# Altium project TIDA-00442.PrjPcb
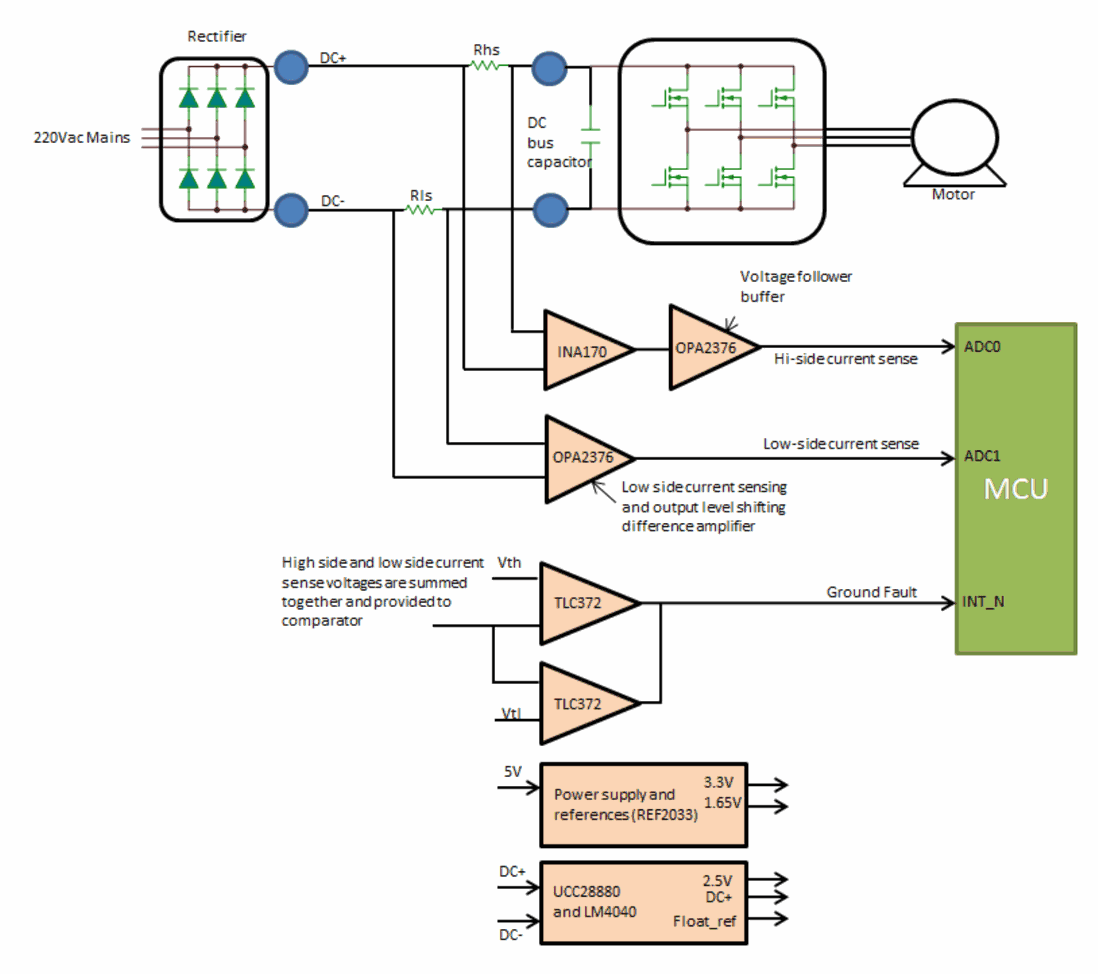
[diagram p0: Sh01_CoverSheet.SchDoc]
CopyrightYear: 2015; EVM_Orderable: N/A; PCB_Layout: Manjunath M; PCB_Rev: E2; PRJ_Customer: Public Release; PRJ_Engineer: Pawan N; PRJ_Number: TIDA-00442; PRJ_Title: Ground Fault Protection for 220Vac Powered Drives; SCH_Rev: E2; TechSupport: http://www.ti.com/support; TIDA: 00442
3 sheets, 96 parts. Net scope: flat (ports and power ports of the same name join across sheets).
Board file: TIDA-00442.PcbDoc
Sheets:
  Sh01_CoverSheet.SchDoc
  Sh02_Current_sense.SchDoc
  Sh03_TID_Hardware.SchDoc

## Sheet Sh01_CoverSheet.SchDoc: Block Diagram
size 431 x 279 mm; Date: Not shown in title block; ApprovedBy: Not shown in title block; CheckedBy: Not shown in title block; Author: Not shown in title block; CompanyName: Not shown in title block; DrawnBy: Pawan N; Engineer: Not shown in title block; Organization: Not shown in title block; Address1: Not shown in title block; Address2: Not shown in title block; Address3: Not shown in title block; Address4: Not shown in title block; DocumentNumber: 1; Revision: Use project parameter SCH_Rev; SheetNumber: 1; SheetTotal: 3; PageSetup: Record=PageOptions¦CenterHorizontal=True¦CenterVertical=True¦PrintScale=1.00¦XCorrection=1.00¦YCorrection=1.00¦PrintKind=0¦BorderSize=5000000¦LeftOffset=0¦BottomOffset=0¦Orientation=2¦PaperLength=1000¦PaperWidth=1000¦Scale=100¦PaperSource=15¦PrintQuality=600¦MediaType=1¦DitherType=10¦PaperKind=Letter¦PrintScaleMode=1

## Sheet Sh02_Current_sense.SchDoc: Current sense and Signal Conditioning
size 431 x 279 mm; Date: Not shown in title block; ApprovedBy: Not shown in title block; CheckedBy: Not shown in title block; Author: Not shown in title block; CompanyName: Not shown in title block; DrawnBy: Pawan N; Engineer: Not shown in title block; Organization: Not shown in title block; Address1: Not shown in title block; Address2: Not shown in title block; Address3: Not shown in title block; Address4: Not shown in title block; DocumentNumber: 1; Revision: Use project parameter SCH_Rev; SheetNumber: 2; SheetTotal: 3; PageSetup: Record=PageOptions¦CenterHorizontal=True¦CenterVertical=True¦PrintScale=0.64¦XCorrection=1.00¦YCorrection=1.00¦PrintKind=0¦BorderSize=5000000¦LeftOffset=0¦BottomOffset=0¦Orientation=2¦PaperLength=1000¦PaperWidth=1000¦Scale=100¦PaperSource=15¦PrintQuality=600¦MediaType=1¦DitherType=10¦PrintScaleMode=1¦PaperKind=Letter¦PaperIndex=1
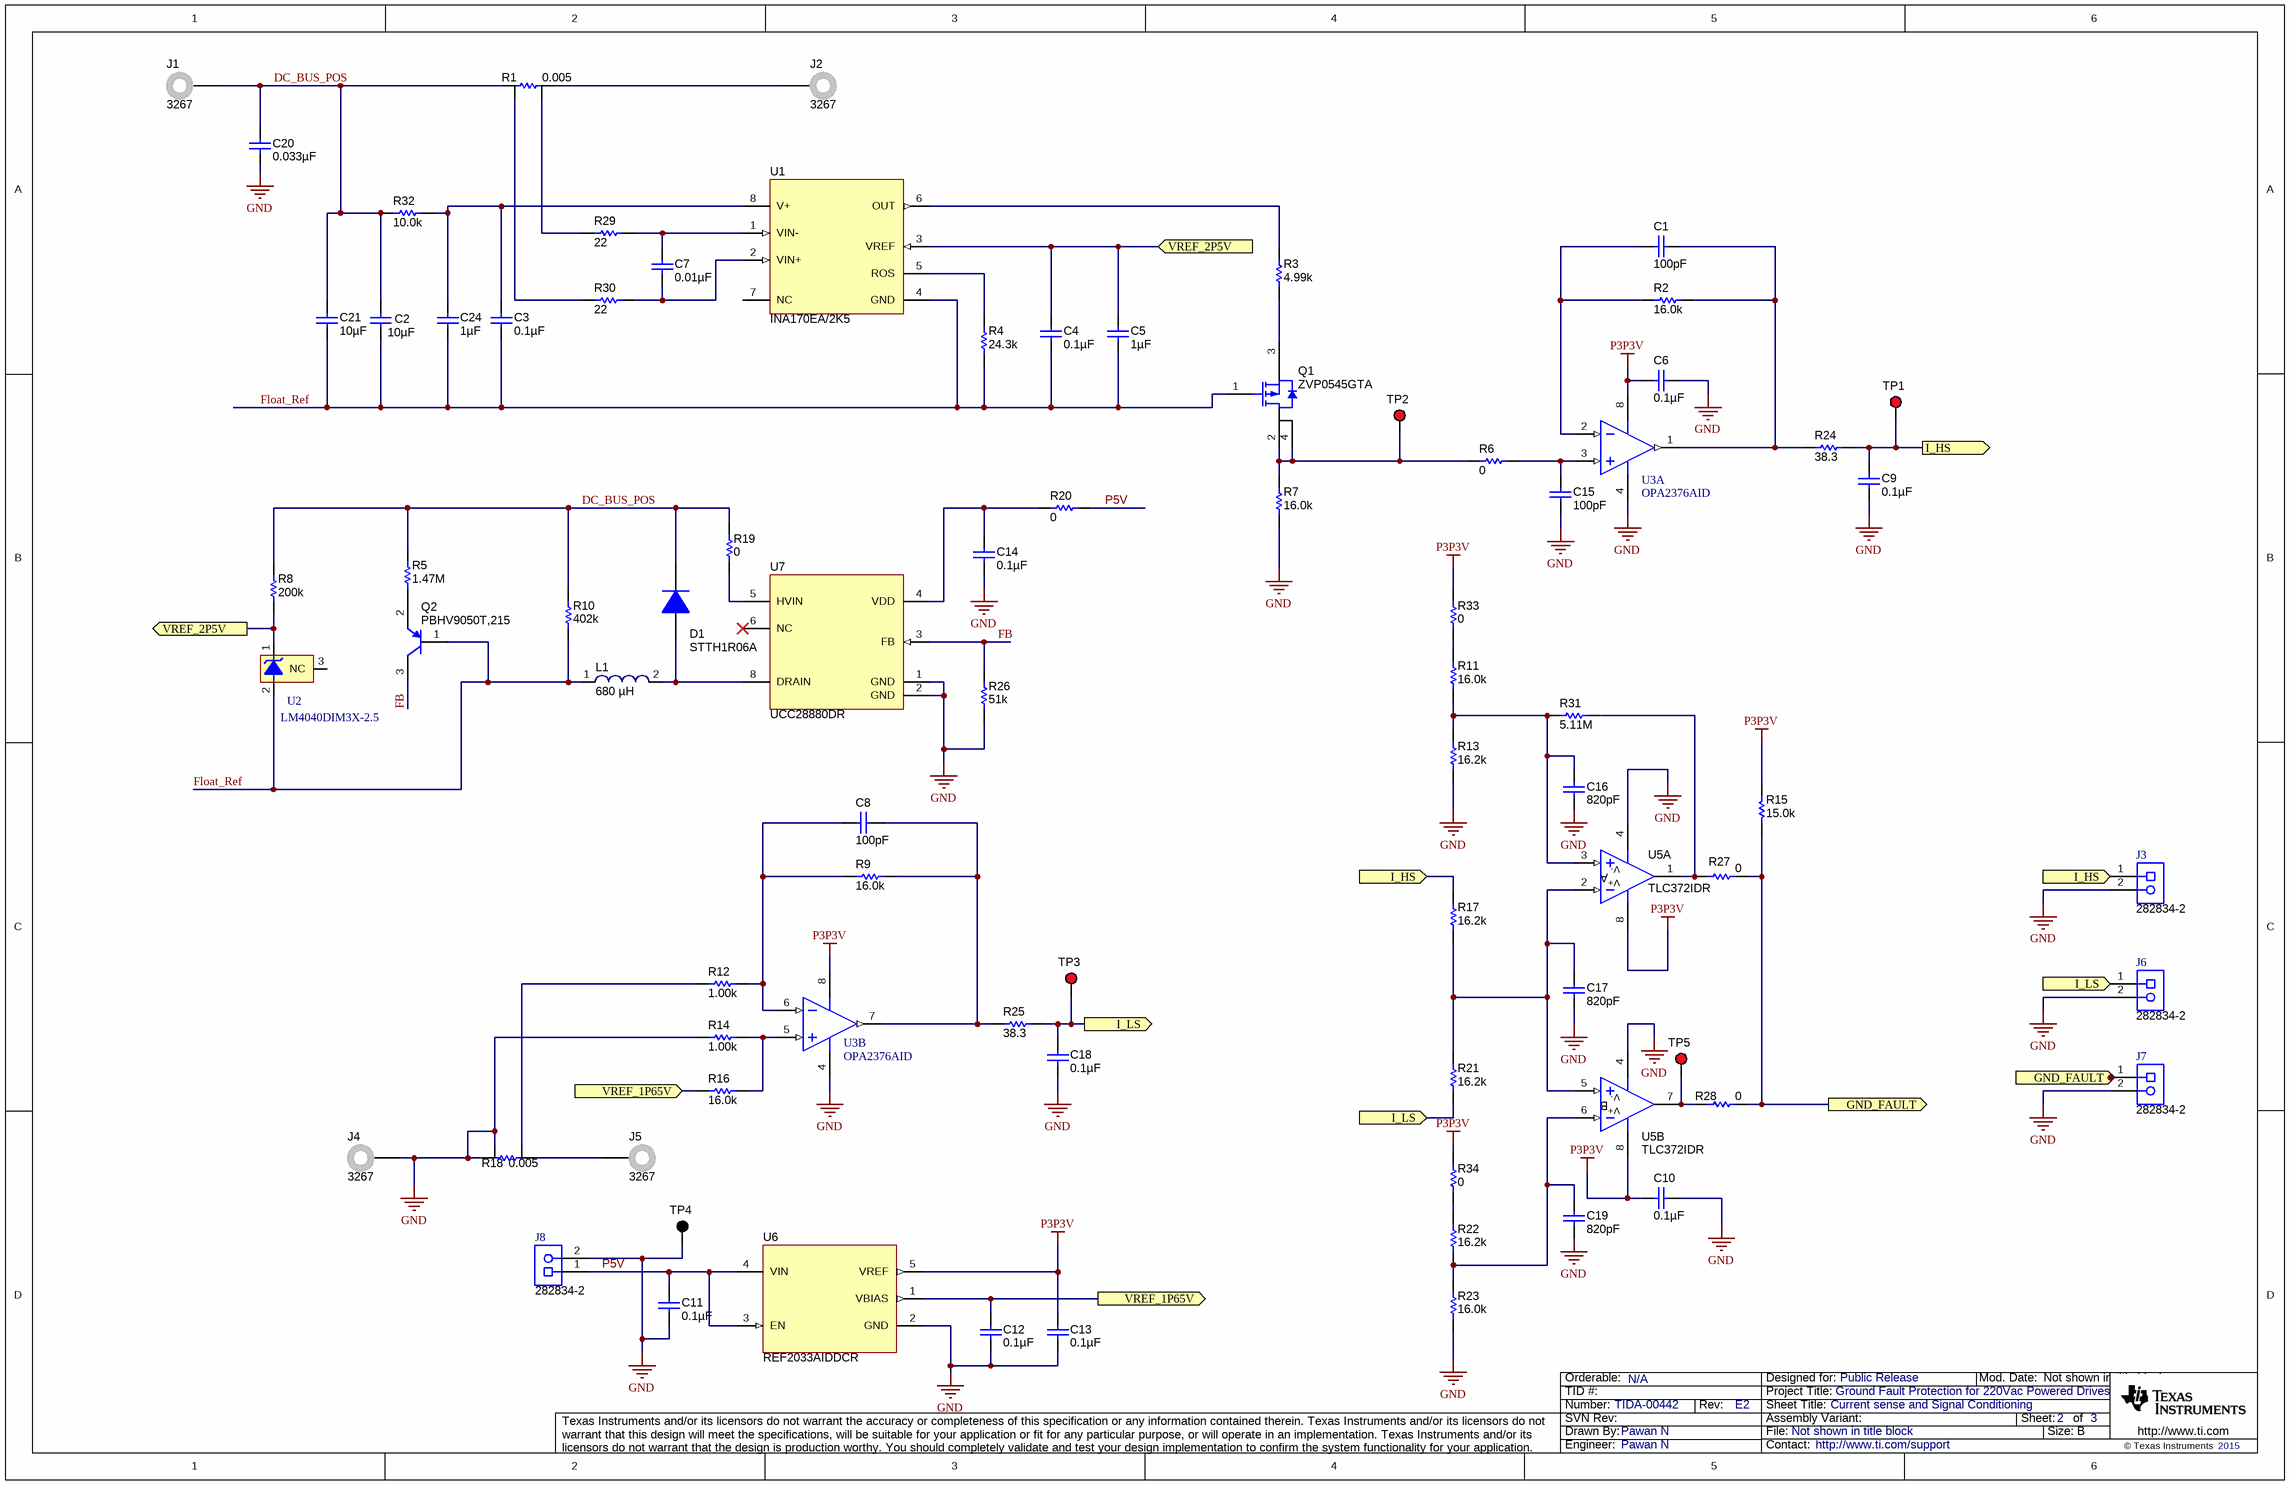
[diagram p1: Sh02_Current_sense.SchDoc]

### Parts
C1  ValueDisplayed: 100pF  [0603]  (hidden comment: GRM1885C1H101JA01D)
C2  ValueDisplayed: 10µF  [1206_190]  (hidden comment: CL31A106KBHNNNE)
C3  ValueDisplayed: 0.1µF  [0603]  (hidden comment: GRM188R71H104KA93D)
C4  ValueDisplayed: 0.1µF  [0603]  (hidden comment: GRM188R71H104KA93D)
C5  ValueDisplayed: 1µF  [0805_HV]  (hidden comment: GRM21BR71H105KA12L)
C6  ValueDisplayed: 0.1µF  [0603]  (hidden comment: GRM188R71H104KA93D)
C7  ValueDisplayed: 0.01µF  [0603]  (hidden comment: 0603ZC103KAT2A)
C8  ValueDisplayed: 100pF  [0603]  (hidden comment: GRM1885C1H101JA01D)
C9  ValueDisplayed: 0.1µF  [0603]  (hidden comment: GRM188R71H104KA93D)
C10  ValueDisplayed: 0.1µF  [0603]  (hidden comment: GRM188R71H104KA93D)
C11  ValueDisplayed: 0.1µF  [0603]  (hidden comment: GRM188R71H104KA93D)
C12  ValueDisplayed: 0.1µF  [0603]  (hidden comment: GRM188R71H104KA93D)
C13  ValueDisplayed: 0.1µF  [0603]  (hidden comment: GRM188R71H104KA93D)
C14  ValueDisplayed: 0.1µF  [0603]  (hidden comment: GRM188R71H104KA93D)
C15  ValueDisplayed: 100pF  [0603]  (hidden comment: GRM1885C1H101JA01D)
C16  ValueDisplayed: 820pF  [0603]  (hidden comment: GRM188R71H821KA01D)
C17  ValueDisplayed: 820pF  [0603]  (hidden comment: GRM188R71H821KA01D)
C18  ValueDisplayed: 0.1µF  [0603]  (hidden comment: GRM188R71H104KA93D)
C19  ValueDisplayed: 820pF  [0603]  (hidden comment: GRM188R71H821KA01D)
C20  ValueDisplayed: 0.033µF  [ECQE_1200x1290x600]  (hidden comment: ECQ-E6333KF)
C21  ValueDisplayed: 10µF  [1206_190]  (hidden comment: CL31A106KBHNNNE)
C24  ValueDisplayed: 1µF  [0805_HV]  (hidden comment: 08055C105KAT2A)
D1  STTH1R06A  [SMA]
J1  3267  [Pomona_3267]
J2  3267  [Pomona_3267]
J3  282834-2  [TEC_282834-2]
J4  3267  [Pomona_3267]
J5  3267  [Pomona_3267]
J6  282834-2  [TEC_282834-2]
J7  282834-2  [TEC_282834-2]
J8  282834-2  [TEC_282834-2]
L1  680 µH  [8095]
Q1  ZVP0545GTA  [SOT-223]
Q2  PBHV9050T,215  [SOT-23]
R1  ValueDisplayed: 0.005  [WSL3637_0.001]  (hidden comment: WSL36375L000FEA)
R2  ValueDisplayed: 16.0k  [0603]  (hidden comment: RC0603FR-0716KL)
R3  ValueDisplayed: 4.99k  [0603]  (hidden comment: CRCW06034K99FKEA)
R4  ValueDisplayed: 24.3k  [0603]  (hidden comment: RT0603BRD0724K3L)
R5  ValueDisplayed: 1.47M  [0603]  (hidden comment: CRCW06031M47FKEA)
R6  ValueDisplayed: 0  [0603]  (hidden comment: RC0603JR-070RL)
R7  ValueDisplayed: 16.0k  [0603]  (hidden comment: RG1608P-163-B-T5)
R8  ValueDisplayed: 200k  [0603]  (hidden comment: CRCW0603200KFKEA)
R9  ValueDisplayed: 16.0k  [0603]  (hidden comment: RG1608P-163-B-T5)
R10  ValueDisplayed: 402k  [0603]  (hidden comment: CRCW0603402KFKEA)
R11  ValueDisplayed: 16.0k  [0603]  (hidden comment: RC0603FR-0716KL)
R12  ValueDisplayed: 1.00k  [0603]  (hidden comment: RG1608P-102-B-T5)
R13  ValueDisplayed: 16.2k  [0603]  (hidden comment: CRCW060316K2FKEA)
R14  ValueDisplayed: 1.00k  [0603]  (hidden comment: RG1608P-102-B-T5)
R15  ValueDisplayed: 15.0k  [0603]  (hidden comment: CRCW060315K0FKEA)
R16  ValueDisplayed: 16.0k  [0603]  (hidden comment: RG1608P-163-B-T5)
R17  ValueDisplayed: 16.2k  [0603]  (hidden comment: CRCW060316K2FKEA)
R18  ValueDisplayed: 0.005  [WSL3637_0.001]  (hidden comment: WSL36375L000FEA)
R19  ValueDisplayed: 0  [0603]  (hidden comment: RC0603JR-070RL)
R20  ValueDisplayed: 0  [0603]  (hidden comment: RC0603JR-070RL)
R21  ValueDisplayed: 16.2k  [0603]  (hidden comment: CRCW060316K2FKEA)
R22  ValueDisplayed: 16.2k  [0603]  (hidden comment: CRCW060316K2FKEA)
R23  ValueDisplayed: 16.0k  [0603]  (hidden comment: RC0603FR-0716KL)
R24  ValueDisplayed: 38.3  [0603]  (hidden comment: CRCW060338R3FKEA)
R25  ValueDisplayed: 38.3  [0603]  (hidden comment: CRCW060338R3FKEA)
R26  ValueDisplayed: 51k  [0603]  (hidden comment: CRCW060351K0JNEA)
R27  ValueDisplayed: 0  [0603]  (hidden comment: RC0603JR-070RL)
R28  ValueDisplayed: 0  [0603]  (hidden comment: RC0603JR-070RL)
R29  ValueDisplayed: 22  [0603]  (hidden comment: CRCW060322R0JNEA)
R30  ValueDisplayed: 22  [0603]  (hidden comment: CRCW060322R0JNEA)
R31  ValueDisplayed: 5.11M  [0603]  (hidden comment: CRCW06035M11FKEA)
R32  ValueDisplayed: 10.0k  [0603]  (hidden comment: RG1608P-103-B-T5)
R33  ValueDisplayed: 0  [0603]  (hidden comment: RC0603JR-070RL)
R34  ValueDisplayed: 0  [0603]  (hidden comment: RC0603JR-070RL)
TP1  5000  [Keystone5000]  (value not drawn)
TP2  5000  [Keystone5000]  (value not drawn)
TP3  5000  [Keystone5000]  (value not drawn)
TP4  5001  [Keystone5001]  (value not drawn)
TP5  5000  [Keystone5000]  (value not drawn)
U1  INA170EA/2K5  [DGK0008A_N]
U2  LM4040DIM3X-2.5  [MF03A_N]
U3  OPA2376AID  [D0008A_N]  (parts A,B of 2)
U5  TLC372IDR  [D0008A_N]  (parts A,B of 2)
U6  REF2033AIDDCR  [DDC0005A_N]
U7  UCC28880DR  [D0007A_N]

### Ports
GND_FAULT, I_HS, I_HS (out), I_LS, VREF_1P65V, VREF_2P5V

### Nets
GND: C6.1 C9.2 C10.1 C11.2 C12.2 C13.2 C14.2 C15.2 C16.1 C17.1 C18.2 C19.1 C20.2 J3.2 J4.1 J6.2 J7.2 J8.2 R7.1 R13.2 R14.1 R18.1 R18.3 R23.2 R26.1 TP4.1 U3.4(V-) U5.4(V-) U6.2(GND) U7.1(GND) U7.2(GND)
P3P3V: C6.2 C10.2 C13.1 R15.1 R33.1 R34.1 U3.8(V+) U5.8(V+) U6.5(VREF)
DC_BUS_POS: C2.1 C20.1 C21.1 D1.1(K) J1.1 R1.2 R5.2 R8.2 R10.2 R19.1 R32.2
FB: Q2.3(C) R26.2 U7.3(FB)
Float_Ref: C2.2 C3.2 C4.2 C5.2 C21.2 C24.2 L1.1 Q1.1(G) Q2.1(B) R4.1 R10.1 U1.4(GND) U2.2(-V)
GND_FAULT: R15.2 R27.2 R28.2 ; port GND_FAULT
I_HS: C9.1 J3.1 R17.1 R24.2 TP1.1 ; port I_HS
I_LS: C18.1 J6.1 R21.2 R25.2 TP3.1 ; port I_LS
P5V: C11.1 J8.1 R20.2 U6.3(EN) U6.4(VIN)
VREF_1P65V: C12.1 R16.2 U6.1(VBIAS) ; port VREF_1P65V
VREF_2P5V: C4.1 C5.1 R8.1 U1.3(VREF) U2.1(+V) ; port VREF_2P5V
NetC1_1: C1.1 R2.2 R24.1 U3.1(OUT_A)
NetC1_2: C1.2 R2.1 U3.2(IN_A-)
NetC3_1: C3.1 C24.1 R32.1 U1.8(V+)
NetC7_1: C7.1 R29.2 U1.1(VIN-)
NetC7_2: C7.2 R30.2 U1.2(VIN+)
NetC8_1: C8.1 R9.2 R25.1 U3.7(OUT_B)
NetC8_2: C8.2 R9.1 R12.1 U3.6(IN_B-)
NetC14_1: C14.1 R20.1 U7.4(VDD)
NetC15_1: C15.1 R6.2 U3.3(IN_A+)
NetC16_2: C16.2 R11.2 R13.1 R31.1 U5.3(IN+)
NetC17_2: C17.2 R17.2 R21.1 U5.2(IN-) U5.5(IN+)
NetC19_2: C19.2 R22.2 R23.1 U5.6(IN-)
NetD1_2: D1.2(A) L1.2 U7.8(DRAIN)
NetJ2_1: J2.1 R1.1
NetJ5_1: J5.1 R18.2
NetQ1_2: Q1.2(D) Q1.4(D) R6.1 R7.2 TP2.1
NetQ1_3: Q1.3(S) R3.1
NetQ2_2: Q2.2(E) R5.1
NetR1_3: R1.3 R29.1
NetR1_4: R1.4 R30.1
NetR3_2: R3.2 U1.6(OUT)
NetR4_2: R4.2 U1.5(ROS)
NetR11_1: R11.1 R33.2
NetR12_2: R12.2 R18.4
NetR14_2: R14.2 R16.1 U3.5(IN_B+)
NetR19_2: R19.2 U7.5(HVIN)
NetR22_1: R22.1 R34.2
NetR27_1: R27.1 R31.2 U5.1(OUT)
NetR28_1: R28.1 TP5.1 U5.7(OUT)

Not connected (* = marked no-connect by the designer): J7 1; U1 7(NC); U2 3(NC); U7 6(NC)*

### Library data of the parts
C1 C8 C15 = GRM1885C1H101JA01D: CAP, CERM, 100 pF, 50 V, +/- 5%, C0G/NP0, 0603; Manufacturer: MuRata; Polarized: N; CompType: Capacitor; Value: 100pF; U/M: EA; Cap_F: 0.0000000001; Tolerance_%: 5; Value1: Unknown; VDC_V: 50; Value2: 50V; TaMin_C: -55; TaMax_C: 125
C2 C21 = CL31A106KBHNNNE: CAP, CERM, 10 µF, 50 V, +/- 10%, X5R, 1206_190; Manufacturer: Samsung Electro-Mechanics; Polarized: N; CompType: Capacitor; Value: 10uF; U/M: EA; Cap_F: 0.00001; Tolerance_%: 10; Value1: Unknown; VDC_V: 50; Value2: 50V; TaMin_C: -55; TaMax_C: 85; Cap_Case: 1206
C3 C4 C6 C9-C14 C18 = GRM188R71H104KA93D: CAP, CERM, 0.1 µF, 50 V, +/- 10%, X7R, 0603; Manufacturer: MuRata; Polarized: N; CompType: Capacitor; Value: 0.1uF; U/M: EA; Cap_F: 0.0000001; Tolerance_%: 10; Value1: Unknown; VDC_V: 50; Value2: 50V; TaMin_C: -55; TaMax_C: 125
C5 = GRM21BR71H105KA12L: CAP, CERM, 1 µF, 50 V, +/- 10%, X7R, 0805; Manufacturer: MuRata; Polarized: N; CompType: Capacitor; Value: 1uF; U/M: EA; Cap_F: 0.000001; Tolerance_%: 10; Value1: Unknown; VDC_V: 50; Value2: 50V; TaMin_C: -55; TaMax_C: 125; Cap_Case: 0805
C7 = 0603ZC103KAT2A: CAP, CERM, 0.01 µF, 10 V, +/- 10%, X7R, 0603; Manufacturer: AVX; Polarized: N; CompType: Capacitor; Value: 0.01uF; U/M: EA; Cap_F: 0.00000001; Tolerance_%: 10; Value1: Unknown; Value2: 10V; TaMin_C: -55; TaMax_C: 125
C16 C17 C19 = GRM188R71H821KA01D: CAP, CERM, 820 pF, 50 V, +/- 10%, X7R, 0603; Manufacturer: MuRata; Polarized: N; CompType: Capacitor; Value: 820pF; U/M: EA; Cap_F: 0.00000000082; Tolerance_%: 10; Value1: Unknown; VDC_V: 50; Value2: 50V; TaMin_C: -55; TaMax_C: 125
C20 = ECQ-E6333KF: CAP, Film, 0.033 µF, 630 V, +/- 10%, TH; Manufacturer: Panasonic; Polarized: N; CompType: Capacitor; Value: 0.033uF; U/M: EA; Cap_F: 0.000000033; Tolerance_%: 10; Value1: Unknown; VDC_V: 630; Value2: 630V; TaMin_C: -40; TaMax_C: 105; Cap_Case: 12x12.9x6mm
C24 = 08055C105KAT2A: CAP, CERM, 1 µF, 50 V, +/- 10%, X7R, 0805; Manufacturer: AVX; Polarized: N; CompType: Capacitor; Value: 1uF; U/M: EA; Cap_F: 0.000001; Tolerance_%: 10; Value1: Unknown; VDC_V: 50; Value2: 50V; TaMin_C: -55; TaMax_C: 125; Cap_Case: 0805
D1 = STTH1R06A: Diode, Ultrafast, 600 V, 1 A, SMA; Manufacturer: STMicroelectronics; U/M: EA; Vf_V: 1; Value: 600V; Value1: 1A; Value2: 1V; Vr_V: 600; TJmax_C: 175; RJC_CperW: 30
J1 J2 J4 J5 = 3267: Standard Banana Jack, Uninsulated; Manufacturer: Pomona Electronics; SymbolCreator: a0412235; CompType: Connector; U/M: EA
J3 J6-J8 = 282834-2: Terminal Block, 2x1, 2.54mm, TH; Manufacturer: TE Connectivity; SymbolCreator: a0412235; U/M: EA
L1 = WE-TI HV 8095, 768772681: SMD-Radial Leaded Wire Wound  Inductor WE-TI HV, L=680 µH; Manufacturer: Würth Elektronik eiSos GmbH
Q1 = ZXMP6A17GTA: MOSFET, P-CH, -450 V, 75 mA, SOT-223; Manufacturer: Diodes Inc.; Alternate Manufacturer: None; SymbolCreator: a0799628; U/M: EA; ChType: P; Value: -60V; VdsMax_V: -60; Value1: 0.19 ohm; Rdson45_ohm: 0.19; Value2: 9 nC; QgTyp_nC: 9; Vgs_V: 20; IdsMax_A: 3
Q2 = PBHV9050T,215, NXP Semiconductor: Transistor, PNP, 500 V, 0.15 A, SOT-23; CompType: BJT; PNP: 1; NPN: 0; Vceo_V: 500; Vcesat1_V: 0.095; Value: 500 V; IcRated_A: 0.15; Value1: 0.15 A; HfeMax: 300; TaMin_C: -55; TaMax_C: 150; U/M: EA
R1 R18 = WSL36371L000FEA: RES, 0.005, 1%, 3 W, WSL3637; Manufacturer: Vishay-Dale; CompType: Resistor; Value: 0.001; Value_Code: 1L000; Tolerance_%: 1; Power_W: 3; Value2: 3W; VDC_V: 0; TempCo: 75 ppm/C; EIA_Code: E96; U/M: EA
R2 R11 R23 = RC0603FR-0716KL: RES, 16.0 k, 1%, 0.1 W, 0603; Manufacturer: Yageo America; CompType: Resistor; Value: 16.0k; Res_ohm: 16000; Value_Code: 16k0; Tolerance_%: 1; Power_W: 0.1; Value2: 0.1W; VDC_V: 150; TempCo: 200 ppm/C; U/M: EA
R3 = CRCW06034K99FKEA: RES, 4.99 k, 1%, 0.1 W, 0603; Manufacturer: Vishay-Dale; CompType: Resistor; Value: 4.99k; Res_ohm: 4990; Value_Code: 4k99; Tolerance_%: 1; Power_W: 0.1; Value2: 0.1W; VDC_V: 75; TempCo: 100 ppm/C; EIA_Code: E96; U/M: EA
R4 = RT0603BRD0724K3L: RES, 24.3 k, 0.1%, 0.1 W, 0603; Manufacturer: Yageo America; CompType: Resistor; Value: 24.3k; Res_ohm: 24300; Value_Code: 24k3; Tolerance_%: 0.1; Value2: 0.1W; VDC_V: 75; TempCo: 25 ppm/C; EIA_Code: E192; U/M: EA
R5 = CRCW06031M47FKEA: RES, 1.47 M, 1%, 0.1 W, 0603; Manufacturer: Vishay-Dale; CompType: Resistor; Value: 1.47Meg; Res_ohm: 1470000; Value_Code: 1M47; Tolerance_%: 1; Power_W: 0.1; Value2: 0.1W; VDC_V: 75; TempCo: 100 ppm/C; EIA_Code: E96; U/M: EA
R6 R19 R20 R27 R28 R33 R34 = RC0603JR-070RL: RES, 0, 5%, 0.1 W, 0603; Manufacturer: Yageo America; CompType: Resistor; Value: 0; Value_Code: 0000; Tolerance_%: 5; Power_W: 0.1; Value2: 0.1W; VDC_V: 50; TempCo: 200 ppm/C; EIA_Code: E24; U/M: EA
R7 R9 R16 = RG1608P-163-B-T5: RES, 16.0 k, 0.1%, 0.1 W, 0603; Manufacturer: Susumu Co Ltd; CompType: Resistor; Value: 16.0k; Res_ohm: 16000; Value_Code: 16k0; Tolerance_%: 0.1; Value2: 0.1W; VDC_V: 75; TempCo: 25 ppm/C; EIA_Code: E192; U/M: EA
R8 = CRCW0603200KFKEA: RES, 200 k, 1%, 0.1 W, 0603; Manufacturer: Vishay-Dale; CompType: Resistor; Value: 200k; Res_ohm: 200000; Tolerance_%: 1; Power_W: 0.1; Value2: 0.1W; VDC_V: 75; TempCo: 100 ppm/C; EIA_Code: E96; U/M: EA
R10 = CRCW0603402KFKEA: RES, 402 k, 1%, 0.1 W, 0603; Manufacturer: Vishay-Dale; CompType: Resistor; Value: 402k; Res_ohm: 402000; Tolerance_%: 1; Power_W: 0.1; Value2: 0.1W; VDC_V: 75; TempCo: 100 ppm/C; EIA_Code: E96; U/M: EA
R12 R14 = RG1608P-102-B-T5: RES, 1.00 k, 0.1%, 0.1 W, 0603; Manufacturer: Susumu Co Ltd; CompType: Resistor; Value: 1.00k; Res_ohm: 1000; Value_Code: 1k00; Tolerance_%: 0.1; Value2: 0.1W; VDC_V: 75; TempCo: 25 ppm/C; EIA_Code: E192; U/M: EA
R13 R17 R21 R22 = CRCW060316K2FKEA: RES, 16.2 k, 1%, 0.1 W, 0603; Manufacturer: Vishay-Dale; CompType: Resistor; Value: 16.2k; Res_ohm: 16200; Value_Code: 16k2; Tolerance_%: 1; Power_W: 0.1; Value2: 0.1W; VDC_V: 75; TempCo: 100 ppm/C; EIA_Code: E96; U/M: EA
R15 = CRCW060315K0FKEA: RES, 15.0 k, 1%, 0.1 W, 0603; Manufacturer: Vishay-Dale; CompType: Resistor; Value: 15.0k; Res_ohm: 15000; Value_Code: 15k0; Tolerance_%: 1; Power_W: 0.1; Value2: 0.1W; VDC_V: 75; TempCo: 100 ppm/C; EIA_Code: E96; U/M: EA
R24 R25 = CRCW060338R3FKEA: RES, 38.3, 1%, 0.1 W, 0603; Manufacturer: Vishay-Dale; CompType: Resistor; Value: 38.3; Value_Code: 38R3; Tolerance_%: 1; Power_W: 0.1; Value2: 0.1W; VDC_V: 75; TempCo: 100 ppm/C; EIA_Code: E96; U/M: EA
R26 = CRCW060351K0JNEA: RES, 51 k, 5%, 0.1 W, 0603; Manufacturer: Vishay-Dale; CompType: Resistor; Value: 51k; Res_ohm: 51000; Value_Code: 51k0; Tolerance_%: 5; Power_W: 0.1; Value2: 0.1W; VDC_V: 75; TempCo: 200 ppm/C; EIA_Code: E24; U/M: EA
R29 R30 = CRCW060322R0JNEA: RES, 22, 5%, 0.1 W, 0603; Manufacturer: Vishay-Dale; CompType: Resistor; Value: 22; Value_Code: 22R0; Tolerance_%: 5; Power_W: 0.1; Value2: 0.1W; VDC_V: 75; TempCo: 200 ppm/C; EIA_Code: E24; U/M: EA
R31 = CRCW06035M11FKEA: RES, 5.11 M, 1%, 0.1 W, 0603; Manufacturer: Vishay-Dale; CompType: Resistor; Value: 5.11Meg; Res_ohm: 5110000; Value_Code: 5M11; Tolerance_%: 1; Power_W: 0.1; Value2: 0.1W; VDC_V: 75; TempCo: 100 ppm/C; EIA_Code: E96; U/M: EA
R32 = RG1608P-103-B-T5: RES, 10.0 k, 0.1%, 0.1 W, 0603; Manufacturer: Susumu Co Ltd; CompType: Resistor; Value: 10.0k; Res_ohm: 10000; Value_Code: 10k0; Tolerance_%: 0.1; Value2: 0.1W; VDC_V: 75; TempCo: 25 ppm/C; EIA_Code: E192; U/M: EA
TP1-TP3 TP5 = 5000: Test Point, Miniature, Red, TH; Manufacturer: Keystone; CompType: Test Point Loop; U/M: EA
TP4 = 5001: Test Point, Miniature, Black, TH; Manufacturer: Keystone; CompType: Test Point Loop; U/M: EA
U1 = INA170EA/2K5: High-Side, Bidirectional Current Shunt Monitor, DGK0008A; Alternate PartNumber: INA170EA/250; Manufacturer: Texas Instruments; SymbolCreator: Altium; CompType: IC; U/M: EA
U2 = LM4040DIM3X-2.5: Precision Micropower Shunt Voltage Reference, 3-pin SOT-23; Manufacturer: Texas Instruments; PackageTopMarking: R2D*XTT; PowerWise: N; CompType: Voltage Reference IC
U3 = OPA2376AID: Precision, Low Noise, Low Quiescent Current Operational Amplifier, 2 to 5.5 V, -40 to 125 degC, 8-pin SOIC (D0008A), Green (RoHS & no Sb/Br); Manufacturer: Texas Instruments; Alternate Manufacturer: None; Alternate PartNumber: Equivalent; CMRR(Min)(dB): 76; IIB(Max)(pA): 10; Iq per channel(Max)(mA): 0.95; Number of Channels: 2; Offset Drift(Typ)(uV/C): 0.32; Sub Family: Low Input Bias Current Amp (<=10pA), Low Noise Amp (<=10nV/rtHz), Low Offset Voltage Amplifier (<=500uV), Low Supply Voltage Amplifier (<=2.7V), Precision Amplifier; Total Supply Voltage(Max)(+5V is 5, +/-5V is 10): 5.5; Vio (25C)(Max)(mV): 0.025; Vn at 1kHz(Typ)(nV/rtHz): 7.5
U5 = TLC372CDR: LinCMOS Dual Differential Comparators, D0008A; Manufacturer: Texas Instruments; SymbolCreator: a0411947; CompType: IC; U/M: EA
U6 = REF2033AIDDCR: Low-Drift, Low-Power, Dual-Output, VREF and VREF / 2 Voltage References, DDC0005A; Alternate PartNumber: REF2033AIDDCT; Manufacturer: Texas Instruments; SymbolCreator: a0799628; CompType: IC; U/M: EA
U7 = UCC28880DR: 700-V Lowest Quiescent Current Off-Line Switcher, D0007A; Manufacturer: Texas Instruments; SymbolCreator: a0411947; CompType: IC; U/M: EA

## Sheet Sh03_TID_Hardware.SchDoc
size 431 x 279 mm; Date: Not shown in title block; ApprovedBy: Not shown in title block; CheckedBy: Not shown in title block; Author: Not shown in title block; CompanyName: Not shown in title block; DrawnBy: Pawan N; Engineer: Not shown in title block; Organization: Not shown in title block; Address1: Not shown in title block; Address2: Not shown in title block; Address3: Not shown in title block; Address4: Not shown in title block; DocumentNumber: 1; Revision: Use project parameter SCH_Rev; SheetNumber: 3; SheetTotal: 3; PageSetup: Record=PageOptions¦CenterHorizontal=True¦CenterVertical=True¦PrintScale=1.00¦XCorrection=1.00¦YCorrection=1.00¦PrintKind=0¦BorderSize=5000000¦LeftOffset=0¦BottomOffset=0¦Orientation=2¦PaperLength=1000¦PaperWidth=1000¦Scale=100¦PaperSource=15¦PrintQuality=600¦MediaType=1¦DitherType=10¦PaperKind=Letter¦PrintScaleMode=1
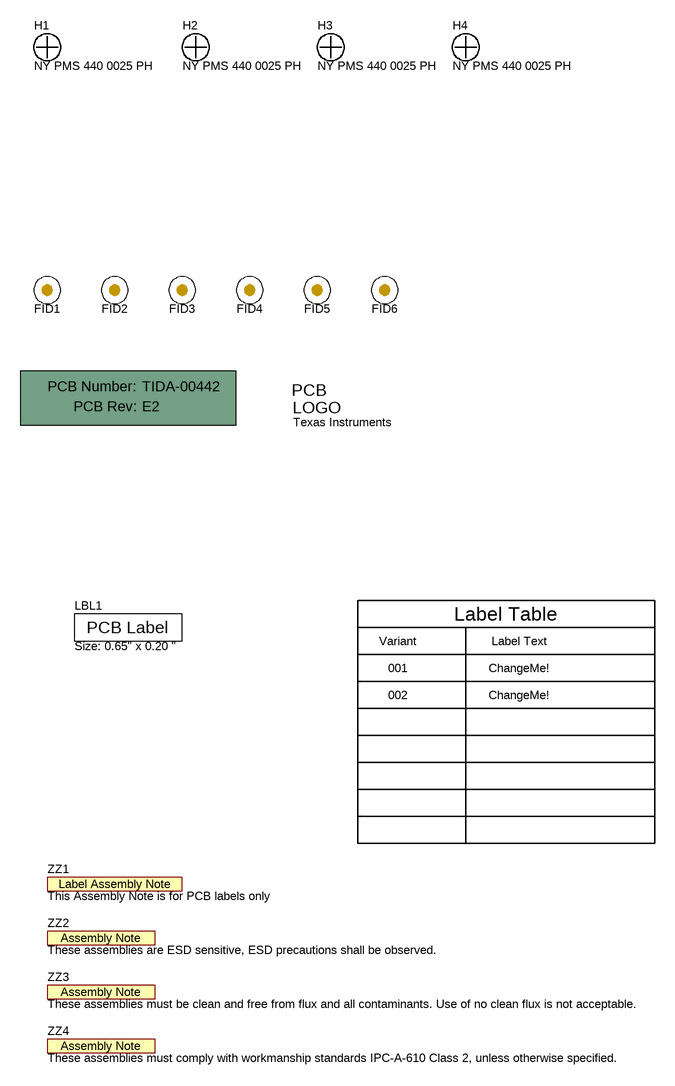
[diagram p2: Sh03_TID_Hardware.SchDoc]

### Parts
!PCB1  Printed Circuit Board  (value not drawn)  (mechanical)
FID1  Fiducial  [Fiducial10-20]  (value not drawn)
FID2  Fiducial  [Fiducial10-20]  (value not drawn)
FID3  Fiducial  [Fiducial10-20]  (value not drawn)
FID4  Fiducial  [Fiducial10-20]  (value not drawn)
FID5  Fiducial  [Fiducial10-20]  (value not drawn)
FID6  Fiducial  [Fiducial10-20]  (value not drawn)
H1  NY PMS 440 0025 PH  [NY PMS 440 0025 PH]
H2  NY PMS 440 0025 PH  [NY PMS 440 0025 PH]
H3  NY PMS 440 0025 PH  [NY PMS 440 0025 PH]
H4  NY PMS 440 0025 PH  [NY PMS 440 0025 PH]
LBL1  Size: 0.65" x 0.20 "  [Label_650x200]
Logo1  Texas Instruments  [TI_Stacked_Overlay_Small]  (no BOM)
ZZ1  This Assembly Note is for PCB labels only  [AssemblyNoteLabel]  (no BOM)
ZZ2  These assemblies are ESD sensitive, ESD precautions shall be observed.  [AssemblyNote]  (no BOM)
ZZ3  These assemblies must be clean and free from flux and all contaminants. Use of no clean flux is not acceptable.  [AssemblyNote]  (no BOM)
ZZ4  These assemblies must comply with workmanship standards IPC-A-610 Class 2, unless otherwise specified.  [AssemblyNote]  (no BOM)

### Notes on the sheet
- Variant
- Label Table
- Label Text
- 001
- 002
- ChangeMe!

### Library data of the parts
!PCB1 = PCB: Manufacturer: Any; PartNumber: TIDA-00442; SymbolCreator: a0412235
FID1-FID6 = Fiducial: Fiducial mark.  There is nothing to buy or mount.; SymbolCreator: codlsc
H1-H4 = NY PMS 440 0025 PH: Machine Screw, Round, #4-40 x 1/4, Nylon, Philips panhead; Manufacturer: B&F Fastener Supply; CompType: Hardware; SymbolCreator: codlsc; U/M: EA
LBL1 = THT-14-423-10: Thermal Transfer Printable Labels, 0.650" W x 0.200" H - 10,000 per roll; Manufacturer: Brady; SymbolCreator: a0412235; CompType: Label
Logo1 = TI_Logo: Texas Instrument Corporate Signature; SymbolCreator: codlsc
ZZ1 = AssemblyNoteLabel: SymbolCreator: a0412235
ZZ2-ZZ4 = AssemblyNote: SymbolCreator: codlsc

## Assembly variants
001: not fitted R20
